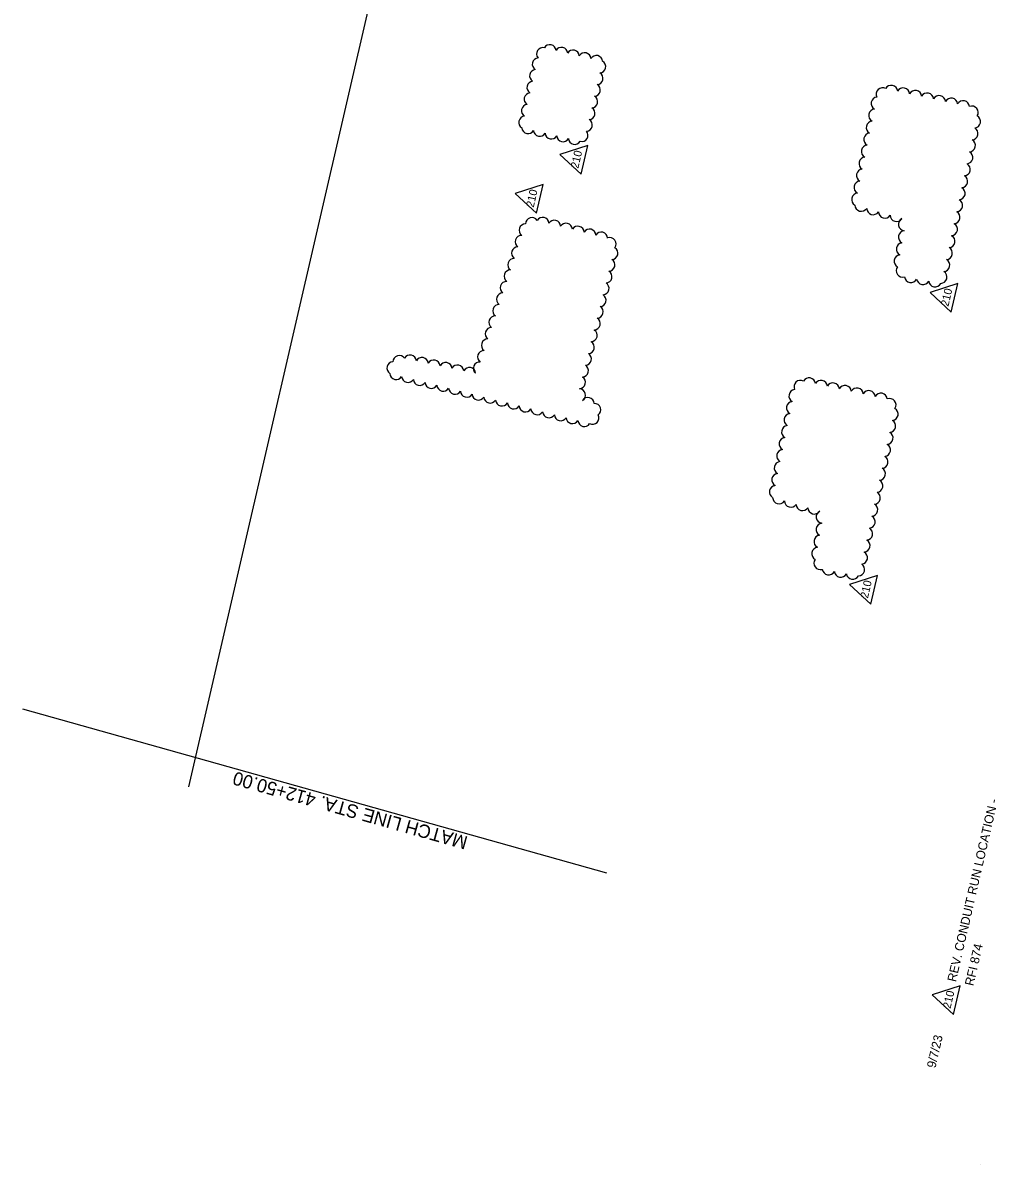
# Model space of a CAD drawing. Extents: x 930148 to 930987, y 617239 to 618551.
# Drawn here: x 930148 to 930732, y 617239 to 617923 of the extents above; entities that cross this region are included whole.
import ezdxf

# ---------------------------------------------------------------- set-up
doc = ezdxf.new("R2010")
doc.units = 0
for name, color, linetype in [('MatchLines_dp', 7, 'Continuous'), ('PlotBorder_dp', 7, 'Continuous'), ('SheetBorder_dp', 7, 'Continuous'), ('TextMinor', 7, 'Continuous'), ('TextShtNo', 7, 'Continuous')]:
    doc.layers.add(name, color=color, linetype=linetype)

msp = doc.modelspace()

# ---------------------------------------------------------------- linework, layer by layer
at = {"layer": 'MatchLines_dp'}
msp.add_line((930498.56, 617413.36), (930148.44, 617511.61), dxfattribs=at)
at = {"layer": 'PlotBorder_dp'}
msp.add_line((930722.59, 617238.93), (930722.59, 617238.93), dxfattribs=at)
at = {"layer": 'TextMinor'}
msp.add_line((930247.9, 617465.07), (930496.64, 618541.42), dxfattribs=at)
at = {"layer": 'TextShtNo'}
for points in [[(930470.43, 617844.08), (930483.15, 617832.3), (930487.13, 617849.49)], [(930443.69, 617820.72), (930456.41, 617808.93), (930460.38, 617826.13)], [(930692.34, 617761.4), (930705.06, 617749.61), (930709.03, 617766.81)], [(930644.06, 617586.39), (930656.78, 617574.6), (930660.75, 617591.8)], [(930693.59, 617340.45), (930706.31, 617328.67), (930710.29, 617345.86)]]:
    msp.add_lwpolyline(points, close=True, dxfattribs=at)
for centre, radius, start, end in [((930460.16, 617904.49), 3.76, 75.3377, 220.3377), ((930464.35, 617906.22), 3.76, 4.48763, 149.48763), ((930471.33, 617904.61), 3.76, 4.48763, 149.48763), ((930478.32, 617902.99), 3.76, 4.48763, 149.48763), ((930457.59, 617898.31), 3.76, 94.48763, 239.48763), ((930485.3, 617901.38), 3.76, 4.48763, 149.48763), ((930492.29, 617899.76), 3.76, 4.48763, 149.48763), ((930494.13, 617896.82), 3.76, 274.48763, 59.48763), ((930455.98, 617891.33), 3.76, 94.48763, 239.48763), ((930492.51, 617889.83), 3.76, 274.48763, 59.48763), ((930454.36, 617884.35), 3.76, 94.48763, 239.48763), ((930490.9, 617882.85), 3.76, 274.48763, 59.48763), ((930669.09, 617881.79), 3.85, 5.43065, 150.43065), ((930452.75, 617877.36), 3.76, 94.48763, 239.48763), ((930489.28, 617875.86), 3.76, 274.48763, 59.48763), ((930663.91, 617880.3), 3.85, 61.58599, 206.58599), ((930676.26, 617880.25), 3.85, 5.43065, 150.43065), ((930683.44, 617878.72), 3.85, 5.43065, 150.43065), ((930690.62, 617877.19), 3.85, 5.43065, 150.43065), ((930697.79, 617875.65), 3.85, 5.43065, 150.43065), ((930451.13, 617870.38), 3.76, 94.48763, 239.48763), ((930487.67, 617868.88), 3.76, 274.48763, 59.48763), ((930660.87, 617874.76), 3.85, 95.99538, 240.99538), ((930704.97, 617874.12), 3.85, 5.43065, 150.43065), ((930712.14, 617872.58), 3.85, 5.43065, 150.43065), ((930717.4, 617869.38), 3.85, 326.82019, 111.82019), ((930449.52, 617863.39), 3.76, 94.48763, 239.48763), ((930486.06, 617861.89), 3.76, 274.48763, 59.48763), ((930659.41, 617867.57), 3.85, 95.99538, 240.99538), ((930718.72, 617863.92), 3.85, 275.43065, 60.43065), ((930451.36, 617860.45), 3.76, 184.48763, 329.48763), ((930458.34, 617858.83), 3.76, 184.48763, 329.48763), ((930657.95, 617860.37), 3.85, 95.99538, 240.99538), ((930717.19, 617856.75), 3.85, 275.43065, 60.43065), ((930465.33, 617857.22), 3.76, 184.48763, 329.48763), ((930472.31, 617855.6), 3.76, 184.48763, 329.48763), ((930479.3, 617853.99), 3.76, 184.48763, 329.48763), ((930483.49, 617855.72), 3.76, 255.3377, 40.3377), ((930656.48, 617853.18), 3.85, 95.99538, 240.99538), ((930715.66, 617849.57), 3.85, 275.43065, 60.43065), ((930655.02, 617845.99), 3.85, 95.99538, 240.99538), ((930714.12, 617842.4), 3.85, 275.43065, 60.43065), ((930653.56, 617838.8), 3.85, 95.99538, 240.99538), ((930712.59, 617835.22), 3.85, 275.43065, 60.43065), ((930652.09, 617831.61), 3.85, 95.99538, 240.99538), ((930711.05, 617828.04), 3.85, 275.43065, 60.43065), ((930650.63, 617824.42), 3.85, 95.99538, 240.99538), ((930709.52, 617820.87), 3.85, 275.43065, 60.43065), ((930649.16, 617817.23), 3.85, 95.99538, 240.99538), ((930651.15, 617813.96), 3.85, 181.35287, 326.35287), ((930658.19, 617811.92), 3.85, 181.35287, 326.35287), ((930707.98, 617813.69), 3.85, 275.43065, 60.43065), ((930453.61, 617802.55), 3.81, 34.19976, 179.19976), ((930460, 617802.7), 3.81, 3.44711, 148.44711), ((930467.05, 617800.94), 3.81, 3.44711, 148.44711), ((930665.24, 617809.87), 3.85, 181.35287, 326.35287), ((930672.29, 617807.83), 3.85, 181.35287, 326.35287), ((930677.26, 617802.29), 3.85, 117.40564, 262.40564), ((930706.45, 617806.52), 3.85, 275.43065, 60.43065), ((930449.76, 617798.8), 3.81, 89.38177, 234.38177), ((930474.09, 617799.17), 3.81, 3.44711, 148.44711), ((930481.14, 617797.41), 3.81, 3.44711, 148.44711), ((930488.18, 617795.65), 3.81, 3.44711, 148.44711), ((930495.23, 617793.88), 3.81, 3.44711, 148.44711), ((930677.24, 617794.66), 3.85, 97.20359, 242.20359), ((930704.92, 617799.34), 3.85, 275.43065, 60.43065), ((930447.5, 617791.89), 3.81, 89.38177, 234.38177), ((930500.27, 617790.52), 3.81, 324.1117, 109.1117), ((930675.93, 617787.44), 3.85, 97.20359, 242.20359), ((930703.38, 617792.16), 3.85, 275.43065, 60.43065), ((930445.24, 617784.99), 3.81, 89.38177, 234.38177), ((930501.36, 617785.04), 3.81, 273.44711, 58.44711), ((930674.62, 617780.22), 3.85, 97.20359, 242.20359), ((930701.85, 617784.99), 3.85, 275.43065, 60.43065), ((930442.98, 617778.09), 3.81, 89.38177, 234.38177), ((930499.6, 617777.99), 3.81, 273.44711, 58.44711), ((930675.89, 617774.5), 3.85, 142.93442, 287.93442), ((930700.31, 617777.81), 3.85, 275.43065, 60.43065), ((930440.73, 617771.19), 3.81, 89.38177, 234.38177), ((930497.84, 617770.95), 3.81, 273.44711, 58.44711), ((930680.89, 617771.32), 3.85, 187.20359, 332.20359), ((930688.11, 617770.01), 3.85, 187.20359, 332.20359), ((930698.59, 617770.75), 3.85, 272.14252, 57.14252), ((930438.47, 617764.29), 3.81, 89.38177, 234.38177), ((930496.07, 617763.9), 3.81, 273.44711, 58.44711), ((930695.33, 617768.69), 3.84, 187.20359, 332.20359), ((930436.21, 617757.38), 3.81, 89.38177, 234.38177), ((930494.31, 617756.86), 3.81, 273.44711, 58.44711), ((930433.95, 617750.48), 3.81, 89.38177, 234.38177), ((930492.55, 617749.81), 3.81, 273.44711, 58.44711), ((930431.69, 617743.58), 3.81, 89.38177, 234.38177), ((930490.78, 617742.77), 3.81, 273.44711, 58.44711), ((930429.43, 617736.68), 3.81, 89.38177, 234.38177), ((930489.02, 617735.72), 3.81, 273.44711, 58.44711), ((930427.17, 617729.77), 3.81, 89.38177, 234.38177), ((930487.26, 617728.68), 3.81, 273.44711, 58.44711), ((930374.13, 617719.88), 3.81, 34.78001, 179.78001), ((930380.58, 617720.18), 3.81, 5.61579, 150.61579), ((930387.68, 617718.68), 3.81, 5.61579, 150.61579), ((930424.92, 617722.87), 3.81, 89.38177, 234.38177), ((930485.49, 617721.63), 3.81, 273.44711, 58.44711), ((930370.52, 617716.09), 3.81, 92.89383, 237.89383), ((930394.79, 617717.19), 3.81, 5.61579, 150.61579), ((930401.9, 617715.69), 3.81, 5.61579, 150.61579), ((930409, 617714.2), 3.81, 5.61579, 150.61579), ((930416.11, 617712.7), 3.81, 5.61579, 150.61579), ((930422.36, 617715.98), 3.81, 84.82189, 229.82189), ((930483.73, 617714.59), 3.81, 273.44711, 58.44711), ((930372.29, 617713.09), 3.81, 183.44711, 328.44711), ((930379.34, 617711.33), 3.81, 183.44711, 328.44711), ((930386.38, 617709.57), 3.81, 183.44711, 328.44711), ((930481.96, 617707.54), 3.81, 273.44711, 58.44711), ((930614.58, 617704.97), 3.85, 61.58599, 206.58599), ((930619.75, 617706.46), 3.85, 5.43065, 150.43065), ((930626.93, 617704.92), 3.85, 5.43065, 150.43065), ((930393.43, 617707.8), 3.81, 183.44711, 328.44711), ((930400.47, 617706.04), 3.81, 183.44711, 328.44711), ((930407.52, 617704.27), 3.81, 183.44711, 328.44711), ((930414.56, 617702.51), 3.81, 183.44711, 328.44711), ((930481.97, 617699.94), 3.81, 301.6045, 86.6045), ((930611.54, 617699.42), 3.85, 95.99538, 240.99538), ((930634.11, 617703.39), 3.85, 5.43065, 150.43065), ((930641.28, 617701.85), 3.85, 5.43065, 150.43065), ((930648.46, 617700.32), 3.85, 5.43065, 150.43065), ((930655.63, 617698.79), 3.85, 5.43065, 150.43065), ((930662.81, 617697.25), 3.85, 5.43065, 150.43065), ((930421.61, 617700.75), 3.81, 183.44711, 328.44711), ((930428.65, 617698.98), 3.81, 183.44711, 328.44711), ((930435.7, 617697.22), 3.81, 183.44711, 328.44711), ((930442.74, 617695.46), 3.81, 183.44711, 328.44711), ((930487.21, 617694.7), 3.81, 3.44711, 148.44711), ((930491.09, 617691.12), 3.81, 306.33668, 91.33668), ((930610.08, 617692.23), 3.85, 95.99538, 240.99538), ((930668.07, 617694.04), 3.85, 326.82019, 111.82019), ((930449.79, 617693.69), 3.81, 183.44711, 328.44711), ((930456.83, 617691.93), 3.81, 183.44711, 328.44711), ((930463.88, 617690.17), 3.81, 183.44711, 328.44711), ((930470.92, 617688.4), 3.81, 183.44711, 328.44711), ((930489.99, 617686.27), 3.81, 242.95262, 27.95262), ((930608.61, 617685.04), 3.85, 95.99538, 240.99538), ((930669.39, 617688.59), 3.85, 275.43065, 60.43065), ((930477.97, 617686.64), 3.81, 183.44711, 328.44711), ((930485.01, 617684.88), 3.81, 183.44711, 328.44711), ((930607.15, 617677.85), 3.85, 95.99538, 240.99538), ((930667.86, 617681.42), 3.85, 275.43065, 60.43065), ((930605.69, 617670.66), 3.85, 95.99538, 240.99538), ((930666.32, 617674.24), 3.85, 275.43065, 60.43065), ((930604.22, 617663.47), 3.85, 95.99538, 240.99538), ((930664.79, 617667.06), 3.85, 275.43065, 60.43065), ((930602.76, 617656.28), 3.85, 95.99538, 240.99538), ((930663.25, 617659.89), 3.85, 275.43065, 60.43065), ((930661.72, 617652.71), 3.85, 275.43065, 60.43065), ((930601.29, 617649.09), 3.85, 95.99538, 240.99538), ((930660.18, 617645.54), 3.85, 275.43065, 60.43065), ((930599.83, 617641.9), 3.85, 95.99538, 240.99538), ((930658.65, 617638.36), 3.85, 275.43065, 60.43065), ((930601.81, 617638.62), 3.85, 181.35287, 326.35287), ((930608.86, 617636.58), 3.85, 181.35287, 326.35287), ((930615.91, 617634.54), 3.85, 181.35287, 326.35287), ((930657.12, 617631.18), 3.85, 275.43065, 60.43065), ((930622.96, 617632.5), 3.85, 181.35287, 326.35287), ((930627.93, 617626.96), 3.85, 117.40564, 262.40564), ((930655.58, 617624.01), 3.85, 275.43065, 60.43065), ((930627.91, 617619.33), 3.85, 97.20359, 242.20359), ((930654.05, 617616.83), 3.85, 275.43065, 60.43065), ((930626.59, 617612.11), 3.85, 97.20359, 242.20359), ((930652.51, 617609.66), 3.85, 275.43065, 60.43065), ((930625.28, 617604.89), 3.85, 97.20359, 242.20359), ((930650.98, 617602.48), 3.85, 275.43065, 60.43065), ((930626.56, 617599.16), 3.85, 142.93442, 287.93442), ((930649.25, 617595.42), 3.85, 272.14252, 57.14252), ((930631.56, 617595.99), 3.85, 187.20359, 332.20359), ((930638.78, 617594.67), 3.85, 187.20359, 332.20359), ((930646, 617593.36), 3.84, 187.20359, 332.20359)]:
    msp.add_arc(centre, radius, start, end, dxfattribs=at)

# ---------------------------------------------------------------- texts
at = {"layer": 'MatchLines_dp'}
msp.add_text('MATCH LINE STA. 412+50.00', height=8, rotation=164.32496, dxfattribs=at).set_placement((930415.73, 617435.16))
at = {"layer": 'SheetBorder_dp'}
for s, p in [('REV. CONDUIT RUN LOCATION - ', (930707.82, 617347.88)), ('RFI 874', (930718.3, 617345.46)), ('9/7/23', (930695.51, 617296.2))]:
    msp.add_text(s, height=5.376, rotation=76.98763, dxfattribs=at).set_placement(p)
at = {"layer": 'TextShtNo'}
for p in [(930481.43, 617835.53), (930454.68, 617812.17), (930703.33, 617752.84), (930655.05, 617577.84), (930704.58, 617331.9)]:
    msp.add_text('210', height=4.799, rotation=76.98764, dxfattribs=at).set_placement(p)

doc.saveas('drawing.dxf')
